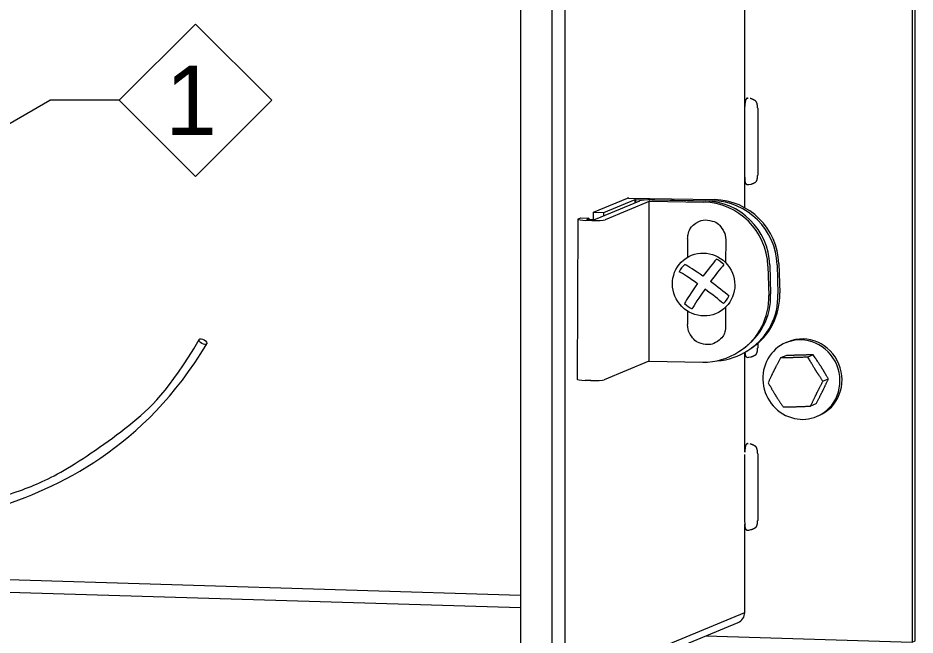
# Model space of a CAD drawing. Extents: x 99862 to 104211, y 98939 to 102076.
# Drawn here: x 102537.9 to 102744.3, y 100806.7 to 100948.7 of the extents above; entities that cross this region are included whole.
import ezdxf

# ---------------------------------------------------------------- set-up
doc = ezdxf.new("R2010")
doc.units = 0
for name, color, linetype in [('Level 1', 7, 'Continuous'), ('Level 11', 7, 'Continuous'), ('Level 15', 7, 'Continuous'), ('Level 18', 7, 'Continuous'), ('Level 19', 7, 'Continuous'), ('Level 20', 7, 'Continuous'), ('Level 22', 7, 'Continuous'), ('Level 30', 7, 'Continuous'), ('Level 6', 7, 'Continuous'), ('Level 9', 7, 'Continuous')]:
    doc.layers.add(name, color=color, linetype=linetype)

msp = doc.modelspace()

# ---------------------------------------------------------------- linework, layer by layer
at = {"layer": 'Level 1'}
for p, q in [((102660.74, 101228.18), (102660.74, 100794.54)), ((102663.81, 100794.74), (102663.81, 101228.38)), ((102653.5, 101220.95), (102653.5, 100802.46)), ((102705.04, 100998.38), (102705.04, 100905.03)), ((102705.13, 100848.77), (102705.13, 100871.72)), ((102705.13, 100811.88), (102705.13, 100832.17)), ((102653.5, 100815.76), (102528.78, 100819.56)), ((102528.78, 100816.78), (102653.5, 100812.99)), ((102705.04, 100811.8), (102663.81, 100794.74)), ((102662.35, 100792.5), (102703.59, 100809.57))]:
    msp.add_line(p, q, dxfattribs=at)
msp.add_arc((102702.63, 100811.88), 2.5, 292.4791, 360, dxfattribs=at)
msp.add_ellipse((102702.63, 100811.88), major_axis=(2.5, 0), ratio=0.112235, start_param=6.018319, end_param=6.283185, dxfattribs=at)
at = {"layer": 'Level 11'}
msp.add_ellipse((102695.66, 100887.33), major_axis=(-4.03, 6.06), ratio=0.979824, dxfattribs=at)
for centre, major_axis, ratio, start_param, end_param in [((102695.65, 100888.54), (4.54, 6.17), 0.069723, 0.774623, 1.506857), ((102695.81, 100887.43), (3.58, -5.39), 0.979824, 1.762443, 2.094403), ((102695.76, 100887.45), (-5.39, -3.58), 0.979824, 4.901469, 5.233429), ((102696.87, 100887.61), (6.17, -4.54), 0.069723, 1.843795, 2.744743), ((102697.37, 100887.27), (-4.54, -6.17), 0.069723, 3.916018, 4.645885), ((102695.6, 100885.89), (-6.17, 4.54), 0.069723, 4.983765, 5.886534), ((102695.65, 100888.54), (4.54, 6.17), 0.069723, 1.787106, 2.744743), ((102696.87, 100887.61), (6.17, -4.54), 0.069723, 0.774623, 1.561852), ((102697.37, 100887.27), (-4.54, -6.17), 0.069723, 4.926025, 5.886534), ((102695.6, 100885.89), (-6.17, 4.54), 0.069723, 3.916018, 4.702017), ((102695.76, 100887.45), (-5.39, -3.58), 0.979824, 1.762443, 2.094403), ((102695.81, 100887.43), (3.58, -5.39), 0.979824, 4.901469, 5.233429)]:
    msp.add_ellipse(centre, major_axis=major_axis, ratio=ratio, start_param=start_param, end_param=end_param, dxfattribs=at)
at = {"layer": 'Level 15'}
for p in [(102508.19, 100908.34), (102561.2, 100929.71)]:
    msp.add_line(p, (102545.2, 100929.71), dxfattribs=at)
at = {"layer": 'Level 18'}
msp.add_line((102743.65, 101000.46), (102743.65, 100805.07), dxfattribs=at)
msp.add_lwpolyline([(102696.2, 100806.51), (102743.65, 100805.07), (102744.31, 100805.34), (102744.31, 101000.44)], dxfattribs=at)
at = {"layer": 'Level 19'}
for p, q in [((102715.12, 100874.14), (102714.63, 100873.94)), ((102714.58, 100870.95), (102713.35, 100870.45)), ((102720.89, 100871.13), (102719.67, 100870.62)), ((102724.35, 100865.58), (102723.13, 100865.07)), ((102721.51, 100859.85), (102720.28, 100859.35)), ((102721.66, 100856.95), (102722.15, 100857.15))]:
    msp.add_line(p, q, dxfattribs=at)
for centre, start_param, end_param in [((102718.15, 100865.45), 3.141593, 6.283185), ((102718.63, 100865.65), 3.141593, 6.283185), ((102718.15, 100865.45), 6.283185, 8.837042), ((102718.15, 100865.45), 2.553857, 3.141593)]:
    msp.add_ellipse(centre, major_axis=(-3.52, 8.5), ratio=0.959029, start_param=start_param, end_param=end_param, dxfattribs=at)
for points in [[(102713.35, 100870.45), (102712.32, 100868.5), (102711.37, 100866.6), (102710.51, 100864.72)], [(102719.67, 100870.62), (102717.48, 100870.53), (102715.37, 100870.47), (102713.35, 100870.45)], [(102720.89, 100871.13), (102718.87, 100871.11), (102716.77, 100871.05), (102714.58, 100870.95)], [(102723.13, 100865.07), (102722.03, 100866.69), (102720.99, 100868.33), (102719.67, 100870.62)], [(102724.35, 100865.58), (102723.41, 100867.26), (102722.38, 100868.91), (102720.89, 100871.13)], [(102710.51, 100864.72), (102711.59, 100862.84), (102712.72, 100860.98), (102713.97, 100859.17)], [(102720.28, 100859.35), (102721.15, 100861.22), (102722.1, 100863.13), (102723.13, 100865.07)], [(102721.51, 100859.85), (102722.54, 100861.8), (102723.49, 100863.7), (102724.35, 100865.58)], [(102713.97, 100859.17), (102715.99, 100859.19), (102718.09, 100859.25), (102720.28, 100859.35)]]:
    msp.add_open_spline(points, degree=2, dxfattribs=at)
at = {"layer": 'Level 20'}
msp.add_lwpolyline([(102578.75, 100947.26), (102596.31, 100929.71), (102578.75, 100912.16), (102561.2, 100929.71)], close=True, dxfattribs=at)
at = {"layer": 'Level 22'}
for p, q in [((102705.72, 100930.22), (102705.7, 100930.22)), ((102705.72, 100930.22), (102705.87, 100930.21)), ((102705.1, 100927.72), (102705.1, 100912.34)), ((102708.1, 100927.9), (102708.1, 100912.51)), ((102705.63, 100910.33), (102705.84, 100910.32)), ((102708.1, 100873.89), (102708.1, 100872.77)), ((102705.63, 100870.58), (102705.84, 100870.57)), ((102705.72, 100850.72), (102705.7, 100850.72)), ((102705.72, 100850.72), (102705.87, 100850.72)), ((102705.1, 100848.23), (102705.1, 100832.85)), ((102708.1, 100848.4), (102708.1, 100833.02)), ((102705.63, 100830.83), (102705.84, 100830.83))]:
    msp.add_line(p, q, dxfattribs=at)
for points in [[(102705.84, 100910.32), (102706.03, 100910.33), (102706.54, 100910.43)], [(102705.84, 100870.57), (102706.03, 100870.58), (102706.54, 100870.69)], [(102705.84, 100830.83), (102706.03, 100830.83), (102706.54, 100830.94)]]:
    msp.add_lwpolyline(points, dxfattribs=at)
for centre in [(102705.83, 100930.22), (102705.83, 100850.73)]:
    msp.add_ellipse(centre, major_axis=(0.129, 0), ratio=0.112235, start_param=3.805799, end_param=5.089246, dxfattribs=at)
for points in [[(102705.7, 100930.22), (102705.4, 100930.05), (102705.21, 100929.39), (102705.12, 100928.27)], [(102708.1, 100927.9), (102708.04, 100929.05), (102707.47, 100929.79), (102706.4, 100930.14)], [(102705.1, 100912.34), (102705.12, 100911.2), (102705.27, 100910.54), (102705.56, 100910.34)], [(102706.56, 100910.42), (102707.54, 100910.75), (102708.06, 100911.44), (102708.1, 100912.51)], [(102706.56, 100870.67), (102707.54, 100871), (102708.06, 100871.69), (102708.1, 100872.77)], [(102705.15, 100871.73), (102705.22, 100871.11), (102705.36, 100870.73), (102705.56, 100870.6)], [(102705.7, 100850.72), (102705.4, 100850.55), (102705.21, 100849.9), (102705.12, 100848.77)], [(102708.1, 100848.4), (102708.04, 100849.55), (102707.47, 100850.3), (102706.4, 100850.64)], [(102706.56, 100830.92), (102707.54, 100831.26), (102708.06, 100831.95), (102708.1, 100833.02)], [(102705.1, 100832.85), (102705.12, 100831.71), (102705.27, 100831.04), (102705.56, 100830.85)]]:
    msp.add_open_spline(points, degree=2, dxfattribs=at)
at = {"layer": 'Level 30'}
msp.add_ellipse((102580.47, 100874.16), major_axis=(-0.86, 0.511), ratio=0.488829, dxfattribs=at)
for points in [[(102499.83, 100833.06), (102501.16, 100833.05), (102501.47, 100833.05), (102504.98, 100832.98), (102508.7, 100832.95), (102518.2, 100834.06), (102523.99, 100835.2), (102538.49, 100839.81), (102547.11, 100843.26), (102564.18, 100854.82), (102572.64, 100862.94), (102579.61, 100874.67)], [(102502.45, 100831.03), (102508.82, 100830.92), (102526.82, 100831.25), (102567.07, 100849.66), (102581.33, 100873.65)]]:
    msp.add_open_spline(points, degree=3, dxfattribs=at)
at = {"layer": 'Level 6'}
for p, q in [((102670.31, 100903.99), (102678.12, 100907.21)), ((102672.73, 100903.91), (102679.93, 100906.89)), ((102678.4, 100907.23), (102698.18, 100906.86)), ((102679.93, 100906.89), (102679.93, 100906.17)), ((102679.94, 100906.9), (102679.97, 100906.92)), ((102679.94, 100906.18), (102679.94, 100906.9)), ((102679.97, 100906.92), (102697.77, 100906.58)), ((102679.97, 100906.92), (102679.97, 100906.19)), ((102670.31, 100903.99), (102672.73, 100903.91)), ((102670.31, 100902.32), (102670.31, 100903.99)), ((102672.73, 100903.2), (102672.73, 100903.91)), ((102712.55, 100891.86), (102712.76, 100885.12)), ((102712.97, 100892.14), (102713.17, 100885.4)), ((102705.86, 100872.17), (102706.28, 100872.45))]:
    msp.add_line(p, q, dxfattribs=at)
for centre, major_axis, ratio, start_param, end_param in [((102678.36, 100907.21), (0.25, 0), 0.112235, 1.403591, 2.876726), ((102679.69, 100906.9), (0.25, 0), 0.112235, 5.949784, 6.11598), ((102697.77, 100891.68), (-8.31, 12.49), 0.979824, 4.147244, 5.686921), ((102698.18, 100891.95), (-8.31, 12.49), 0.979824, 4.14725, 5.686921), ((102697.97, 100884.94), (-8.31, 12.49), 0.979824, 3.141593, 4.147252), ((102698.39, 100885.22), (-8.31, 12.49), 0.979824, 3.141593, 4.147252), ((102697.56, 100884.66), (8.31, -12.49), 0.979824, 5.770467, 6.283185)]:
    msp.add_ellipse(centre, major_axis=major_axis, ratio=ratio, start_param=start_param, end_param=end_param, dxfattribs=at)
at = {"layer": 'Level 9'}
for p, q in [((102670.78, 100902.39), (102680.95, 100906.6)), ((102683.29, 100906.5), (102673.02, 100902.24)), ((102683.13, 100869.7), (102683.13, 100906.5)), ((102683.3, 100906.5), (102683.29, 100906.5)), ((102683.3, 100906.5), (102683.34, 100906.52)), ((102683.34, 100906.52), (102695.66, 100906.29)), ((102683.78, 100906.8), (102696.08, 100906.57)), ((102666.75, 100902.36), (102666.54, 100865.53)), ((102666.84, 100902.43), (102667.42, 100902.67)), ((102667.42, 100902.67), (102669.24, 100902.61)), ((102669.95, 100902.05), (102668.6, 100902.09)), ((102669.24, 100902.61), (102668.83, 100902.45)), ((102668.83, 100902.45), (102668.83, 100902.39)), ((102669.24, 100902.61), (102669.24, 100902.33)), ((102669.53, 100902.31), (102669.55, 100902.31)), ((102691.98, 100897.88), (102691.98, 100893.61)), ((102700.74, 100897.59), (102700.72, 100892.37)), ((102710.45, 100891.57), (102710.66, 100884.83)), ((102710.86, 100891.85), (102711.07, 100885.11)), ((102691.98, 100881.19), (102691.98, 100878.1)), ((102700.69, 100882.07), (102700.67, 100877.05)), ((102703.76, 100871.88), (102704.18, 100872.16)), ((102683.08, 100869.67), (102672.81, 100865.42)), ((102683.09, 100869.67), (102683.08, 100869.67)), ((102683.09, 100869.67), (102683.13, 100869.7)), ((102683.13, 100869.7), (102695.46, 100869.47)), ((102669.74, 100865.22), (102668.39, 100865.26))]:
    msp.add_line(p, q, dxfattribs=at)
for centre, major_axis, ratio, start_param, end_param in [((102683.36, 100906.52), (-2.5, 0), 0.112235, 4.545184, 6.018319), ((102695.66, 100891.38), (-8.31, 12.49), 0.979824, 4.147247, 5.686921), ((102696.08, 100891.66), (-8.31, 12.49), 0.979824, 4.147247, 5.686921), ((102669.25, 100902.36), (-2.5, 0), 0.112235, 6.018319, 6.283185), ((102669.25, 100902.36), (-2.5, 0), 0.112235, 6.283185, 7.589115), ((102669.8, 100902.42), (1, 0), 0.112235, 2.876726, 3.141593), ((102669.8, 100902.42), (1, 0), 0.112235, 3.141593, 4.447522), ((102669.81, 100902.42), (1, 0), 0.112235, 4.447522, 6.018319), ((102670.6, 100902.32), (-2.5, 0), 0.112235, 1.30593, 2.876726), ((102695.87, 100884.65), (-8.31, 12.49), 0.979824, 3.141593, 4.147254), ((102696.29, 100884.92), (-8.31, 12.49), 0.979824, 3.141593, 4.14725), ((102695.46, 100884.37), (8.31, -12.49), 0.979824, 5.686921, 6.283185), ((102669.04, 100865.53), (-2.5, 0), 0.112235, 0, 1.30593), ((102670.4, 100865.49), (-2.5, 0), 0.112235, 1.30593, 2.876726)]:
    msp.add_ellipse(centre, major_axis=major_axis, ratio=ratio, start_param=start_param, end_param=end_param, dxfattribs=at)
for points in [[(102691.98, 100897.88), (102691.98, 100898.15), (102692.01, 100898.43), (102692.28, 100899.86), (102692.93, 100900.84), (102693.88, 100901.47)], [(102693.88, 100901.47), (102694.82, 100902.1), (102695.98, 100902.32), (102698.27, 100901.84), (102699.3, 100901.14), (102700.48, 100899.37), (102700.74, 100898.48), (102700.74, 100897.59)], [(102700.67, 100877.05), (102700.67, 100877.03), (102700.67, 100877.01), (102700.44, 100875.84), (102699.79, 100874.86), (102697.9, 100873.6), (102696.74, 100873.38), (102694.45, 100873.86), (102693.42, 100874.56), (102692.24, 100876.32), (102691.98, 100877.21), (102691.98, 100878.1)]]:
    msp.add_open_spline(points, degree=3, dxfattribs=at)

# ---------------------------------------------------------------- texts
at = {"layer": 'Level 20'}
msp.add_text('1', height=16, dxfattribs=at).set_placement((102571.8, 100921.71))

doc.saveas('drawing.dxf')
